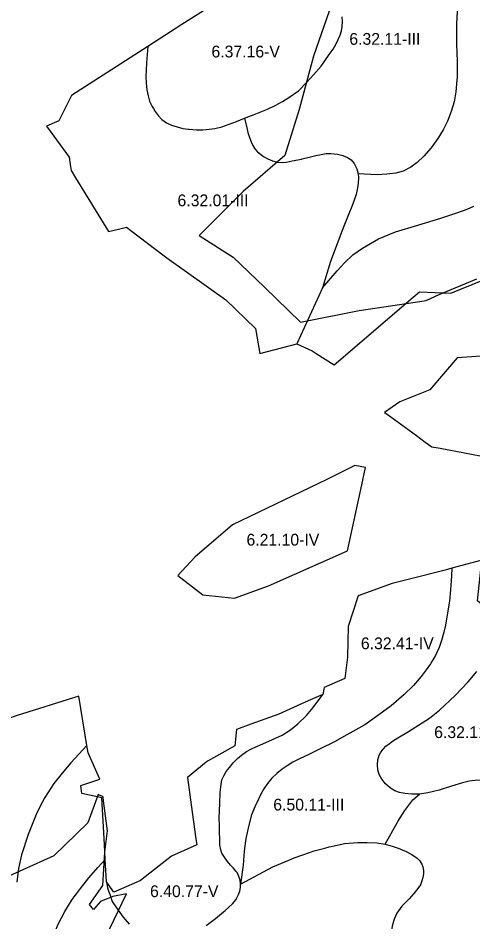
# Model space of a CAD drawing. Extents: x -555156 to -540209, y -1046851 to -1035695.
# Drawn here: x -543499 to -543114, y -1038962 to -1038196 of the extents above; entities that cross this region are included whole.
import ezdxf

# ---------------------------------------------------------------- set-up
doc = ezdxf.new("R2010")
doc.units = 0
for name, color, linetype in [('Vrstva 27', 7, 'Continuous'), ('Vrstva 28', 7, 'Continuous'), ('Vrstva 29', 7, 'Continuous')]:
    doc.layers.add(name, color=color, linetype=linetype)

msp = doc.modelspace()

# ---------------------------------------------------------------- linework, layer by layer
at = {"layer": 'Vrstva 28'}
for points in [[(-543306.54, -1038145.7), (-543311.34, -1038156.06), (-543320.71, -1038176.28), (-543360.37, -1038201.68), (-543389.3, -1038220.26)], [(-543126.82, -1038185.64), (-543127.72, -1038201.18), (-543127.57, -1038220.01), (-543127.42, -1038224.12), (-543127.31, -1038227.25), (-543127.16, -1038231.32), (-543127.16, -1038244.58), (-543127.16, -1038246.41), (-543127.36, -1038248.77), (-543128.2, -1038258.67), (-543129.55, -1038267.33), (-543132.09, -1038275.4), (-543135.37, -1038283.62), (-543138.96, -1038290.95), (-543143.59, -1038298.42), (-543149.26, -1038306.34)], [(-543307.24, -1038281.11), (-543297.76, -1038277.43), (-543287.86, -1038273.42), (-543281.37, -1038270.34), (-543275.14, -1038267.01), (-543269.68, -1038263.59), (-543261.65, -1038257.96), (-543254.66, -1038250.96), (-543248.77, -1038244.47), (-543242.45, -1038237.12), (-543235.45, -1038227.13), (-543232.28, -1038222.61), (-543229.89, -1038218.51), (-543227.84, -1038214.5), (-543226.22, -1038210.82), (-543225.03, -1038207.07), (-543224.51, -1038203.39), (-543224.34, -1038199.29), (-543224.69, -1038195.19)], [(-543389.3, -1038220.26), (-543453.96, -1038261.78), (-543464.75, -1038283.22), (-543475.03, -1038287.86), (-543468.76, -1038296.39), (-543455.75, -1038314.11), (-543454.92, -1038320.27), (-543454.23, -1038325.37), (-543450.41, -1038331.59), (-543422.48, -1038377.07), (-543414.21, -1038375.05), (-543407.26, -1038373.36), (-543403.54, -1038376.2), (-543375.29, -1038397.75), (-543373.03, -1038399.46), (-543323.25, -1038434.93), (-543297.87, -1038459.37), (-543294.19, -1038480.59), (-543263.03, -1038472.23)], [(-543389.3, -1038220.26), (-543390.36, -1038234.02), (-543390.61, -1038240.57), (-543390.78, -1038245.69), (-543390.53, -1038251.5), (-543389.93, -1038257.05), (-543388.99, -1038262.09), (-543387.71, -1038266.79), (-543385.58, -1038271.23), (-543384.5, -1038272.96), (-543383.04, -1038275.31), (-543380.39, -1038278.72), (-543377.23, -1038282.14), (-543373.48, -1038284.96), (-543369.12, -1038287.09), (-543364.43, -1038288.54), (-543359.65, -1038289.74), (-543355.11, -1038290.37), (-543354.1, -1038290.51)], [(-543342.75, -1038290.85), (-543336.86, -1038290.51), (-543332.59, -1038289.91), (-543326.53, -1038288.37), (-543320.3, -1038286.24), (-543314.16, -1038283.85), (-543307.24, -1038281.11)], [(-543307.24, -1038281.11), (-543305.22, -1038289.31), (-543304.36, -1038293.15), (-543303.17, -1038297.34), (-543301.8, -1038301.1), (-543300.35, -1038304.26), (-543298.64, -1038306.96), (-543298.56, -1038307.08), (-543296.62, -1038309.22), (-543296.17, -1038309.72), (-543291.3, -1038313.48), (-543287.55, -1038315.61), (-543283.71, -1038317.32), (-543279.44, -1038318.26), (-543275.34, -1038318.52), (-543272.01, -1038318.26), (-543266.89, -1038317.32), (-543258.98, -1038315.7), (-543258.53, -1038315.61), (-543252.55, -1038314.16), (-543251.26, -1038313.82), (-543246.75, -1038312.63), (-543242.42, -1038311.79), (-543238.06, -1038311.11), (-543234.05, -1038311.11), (-543228.51, -1038311.62), (-543223.98, -1038312.65), (-543220.14, -1038314.44), (-543216.98, -1038316.49), (-543214.51, -1038319.48), (-543212.2, -1038324.09), (-543211.01, -1038328.19)], [(-543354.1, -1038290.51), (-543348.04, -1038290.93), (-543342.75, -1038290.85)], [(-543149.26, -1038306.34), (-543155.39, -1038313.22), (-543160.91, -1038318.6), (-543166.44, -1038322.63), (-543173.01, -1038325.92), (-543178.99, -1038327.56), (-543186.6, -1038328.61), (-543194.82, -1038329.06), (-543211.01, -1038328.19)], [(-543211.01, -1038328.19), (-543210.75, -1038331.69), (-543210.92, -1038336.13), (-543211.61, -1038339.98), (-543212.8, -1038345.78), (-543215.79, -1038354.41), (-543223.17, -1038372.69), (-543234.41, -1038402.5), (-543241.2, -1038424.73)], [(-543241.2, -1038424.73), (-543228.73, -1038410.4), (-543222.45, -1038403.53), (-543215.43, -1038396.8), (-543207.37, -1038391.12), (-543193.77, -1038383.35), (-543179.44, -1038377.37), (-543160.47, -1038371.69), (-543141.05, -1038365.72), (-543126.56, -1038360.93), (-543118.57, -1038358.1), (-543113.04, -1038355.55)], [(-543263.03, -1038472.23), (-543250.1, -1038478.12), (-543246.54, -1038480.4), (-543231.45, -1038490.04), (-543164.36, -1038432.83), (-543158.92, -1038428.19), (-543132.38, -1038429.44), (-543105.34, -1038418.33), (-543080.91, -1038423.27), (-543024.69, -1038431.13), (-543021.95, -1038430.62), (-543016.98, -1038429.69), (-543005.4, -1038427.54)], [(-543241.2, -1038424.73), (-543263.03, -1038472.23)], [(-542912.45, -1038432.16), (-542946.17, -1038466.68), (-542990.21, -1038499.06), (-543028.67, -1038507.04), (-543056.48, -1038513.32), (-543057.35, -1038510.27), (-543067.77, -1038492.27), (-543090.66, -1038481.63), (-543127.25, -1038484.21), (-543150.42, -1038511.38), (-543175.81, -1038521.33), (-543188.66, -1038530.47), (-543186.57, -1038531.98), (-543161.63, -1038550.02), (-543154.1, -1038555.47), (-543148.54, -1038559.49), (-543141.66, -1038560.78), (-543100.26, -1038568.53)], [(-543287.03, -1038677.48), (-543220.04, -1038647.62), (-543207.87, -1038591.72), (-543204.7, -1038577.15), (-543213.92, -1038575.35), (-543237.55, -1038587.32), (-543317.53, -1038625.76), (-543349.47, -1038653.02), (-543363.91, -1038668.71), (-543342.61, -1038685.04)], [(-543087.57, -1038708.69), (-543091.56, -1038705.35), (-543109.93, -1038689.94), (-543106.21, -1038655.66), (-543131.59, -1038662.42)], [(-543131.59, -1038662.42), (-543131.86, -1038668.88), (-543132.75, -1038680.83), (-543133.65, -1038690.25), (-543135.29, -1038700.26), (-543137.14, -1038710.77), (-543138.5, -1038716.49), (-543140.3, -1038723.58), (-543142.43, -1038729.64), (-543144.31, -1038733.91), (-543145.86, -1038736.87), (-543146.78, -1038738.61), (-543148.54, -1038741.38), (-543149.77, -1038743.3), (-543153.27, -1038748.6), (-543157.71, -1038754.15), (-543164.11, -1038761.83), (-543172.32, -1038769.75), (-543183.08, -1038779.02), (-543193.38, -1038786.64), (-543205.48, -1038795.16), (-543220.57, -1038803.53), (-543231.12, -1038809.52), (-543243.07, -1038815.34), (-543253.37, -1038820.43), (-543260.03, -1038823.77), (-543266.34, -1038826.84), (-543271.12, -1038829.75), (-543275.3, -1038832.56), (-543279.83, -1038836.32), (-543284.18, -1038840.42), (-543287.85, -1038844.78), (-543290.84, -1038849.22), (-543293.57, -1038854), (-543297.14, -1038861.71), (-543297.3, -1038862.08), (-543301.32, -1038871.27), (-543303.56, -1038880.24), (-543306.25, -1038891.45), (-543307.59, -1038902.21), (-543308.31, -1038914.01)], [(-543131.59, -1038662.42), (-543137.34, -1038663.95), (-543165.27, -1038671.06), (-543182.1, -1038675.34), (-543211.11, -1038685.71), (-543219.39, -1038711.71), (-543219.96, -1038737.86), (-543222.27, -1038755.98), (-543239.81, -1038763.44), (-543241.05, -1038769.29)], [(-543342.61, -1038685.04), (-543315.92, -1038687.81), (-543287.03, -1038677.48)], [(-543171.39, -1038853.4), (-543176.09, -1038852.46), (-543180.01, -1038850.92), (-543183.75, -1038848.75), (-543187.93, -1038845.25), (-543190.92, -1038841.15), (-543193.31, -1038837.13), (-543194.33, -1038833.12), (-543194.76, -1038829.02), (-543194.25, -1038824.75), (-543193.58, -1038821.92), (-543193.48, -1038821.51), (-543192.11, -1038818.77), (-543190.06, -1038815.95), (-543189.61, -1038815.48), (-543187.5, -1038813.31), (-543184.6, -1038810.92), (-543181.87, -1038809.04), (-543177.32, -1038806.11), (-543168.36, -1038800.65), (-543156.67, -1038793.56), (-543150.44, -1038789.37), (-543142.19, -1038782.69), (-543128.9, -1038770.29), (-543117.84, -1038758.63), (-543110.37, -1038749.96)], [(-543440.9, -1038812.65), (-543447.7, -1038770.92), (-543499.85, -1038787.23), (-543508.08, -1038790.04), (-543529.87, -1038797.48), (-543592.87, -1038819), (-543585.18, -1038878.96), (-543585.35, -1038882.89), (-543586.72, -1038882.37), (-543597.27, -1038878.34), (-543646.7, -1038859.49)], [(-543241.05, -1038769.29), (-543253.33, -1038774.78), (-543278.32, -1038785.94), (-543302.02, -1038794.69), (-543314.21, -1038799.19), (-543315.58, -1038812.87), (-543319.58, -1038815.13), (-543338.15, -1038825.61), (-543339.67, -1038826.85), (-543355.5, -1038839.81), (-543352.38, -1038862.99), (-543348.5, -1038891.8), (-543347.83, -1038896.74), (-543369.13, -1038906.45), (-543387.45, -1038920.91), (-543395.31, -1038927.11), (-543401.21, -1038929.62), (-543418.06, -1038936.78), (-543424.24, -1038928.03)], [(-543310.61, -1038930.05), (-543311.1, -1038926.78), (-543311.73, -1038924.34), (-543312.66, -1038921.95), (-543313.93, -1038919.99), (-543314.63, -1038919.04), (-543315.29, -1038918.14), (-543316.95, -1038916.33), (-543319.21, -1038913.98), (-543321.6, -1038910.99), (-543324.33, -1038907.32), (-543326.38, -1038903.99), (-543327.4, -1038900.91), (-543328.17, -1038897.15), (-543328.34, -1038892.68), (-543328.45, -1038885.36), (-543328.49, -1038882.96), (-543328.58, -1038880.33), (-543328.79, -1038873.85), (-543328.34, -1038861.89), (-543327.92, -1038852.26), (-543327.16, -1038845.59), (-543326.39, -1038841.84), (-543324.68, -1038837.74), (-543322.89, -1038834.75), (-543320.07, -1038831.16), (-543316.83, -1038827.32), (-543314.54, -1038825.03), (-543313.16, -1038823.65), (-543309.74, -1038820.74), (-543305.56, -1038817.84), (-543302.06, -1038815.79), (-543298.39, -1038814.08), (-543291.73, -1038811.14), (-543283.7, -1038807.59), (-543275.34, -1038804), (-543268.47, -1038799.37), (-543262.05, -1038794.14), (-543254.73, -1038787.26), (-543249.2, -1038780.54), (-543241.05, -1038769.29)], [(-543440.9, -1038812.65), (-543454.53, -1038827.33), (-543461.85, -1038836), (-543468.72, -1038844.97), (-543476.55, -1038856.77), (-543480.33, -1038864.11), (-543483.87, -1038870.97)], [(-543425.31, -1038909.28), (-543426.05, -1038896.39), (-543428.32, -1038856.88), (-543445.21, -1038853.37), (-543446.06, -1038846.44), (-543429.99, -1038841.27), (-543439.89, -1038818.85), (-543440.9, -1038812.65)], [(-543056.55, -1038860.56), (-543079.66, -1038848.97), (-543088.71, -1038845.38), (-543095.8, -1038843.33), (-543100.4, -1038842.65), (-543106.55, -1038842.14), (-543111.84, -1038842.39), (-543116.96, -1038842.99), (-543122.51, -1038844.18), (-543131.79, -1038847), (-543142.4, -1038850.44), (-543151.96, -1038852.83), (-543159.1, -1038853.91)], [(-543188.03, -1038896.26), (-543177.56, -1038877.56), (-543177.27, -1038877.05), (-543171.45, -1038867.63), (-543164.73, -1038858.66), (-543159.1, -1038853.91)], [(-543159.1, -1038853.91), (-543165.5, -1038853.91), (-543171.39, -1038853.4)], [(-543483.87, -1038870.97), (-543490.59, -1038888.01), (-543496.12, -1038905.35), (-543498.66, -1038916.85), (-543500.33, -1038928.3)], [(-543310.61, -1038930.05), (-543283.2, -1038915.37), (-543269.88, -1038909.87), (-543265.12, -1038907.9), (-543257.97, -1038905.37), (-543248.24, -1038901.92), (-543239.37, -1038899.61), (-543235.53, -1038898.61), (-543233.9, -1038898.19), (-543222.55, -1038895.64), (-543211.35, -1038894.75), (-543203.3, -1038894.73), (-543195.28, -1038895.15), (-543188.03, -1038896.26)], [(-543188.03, -1038896.26), (-543182.31, -1038897.89), (-543177.02, -1038899.68), (-543170.36, -1038902.41), (-543165.41, -1038905.06), (-543161.1, -1038908.01), (-543158.62, -1038910.45), (-543156.96, -1038913.14), (-543156.08, -1038915.48), (-543155.54, -1038918.41), (-543155.59, -1038921.48), (-543156.13, -1038924.6), (-543157.06, -1038927.39), (-543158.32, -1038930.56), (-543160.32, -1038933.83), (-543163.74, -1038938.02), (-543167.93, -1038942.46), (-543173.9, -1038948.69), (-543178.25, -1038954.75), (-543180.47, -1038959.88), (-543182.27, -1038965.68), (-543183.46, -1038972.77)], [(-543470.41, -1038976.57), (-543465.2, -1038963.96), (-543459.67, -1038953.2), (-543453.4, -1038943.18), (-543451.55, -1038940.75), (-543449.67, -1038938.28), (-543447.17, -1038935.01), (-543446.23, -1038933.77), (-543439.21, -1038924.8), (-543431.59, -1038915.98), (-543425.31, -1038909.28)], [(-543424.24, -1038928.03), (-543425.31, -1038909.28)], [(-543308.31, -1038914.01), (-543310.61, -1038930.05)], [(-543424.24, -1038928.03), (-543423.5, -1038933.15), (-543421.95, -1038937.35), (-543421.45, -1038938.7), (-543419.31, -1038944.68), (-543415.82, -1038950.23), (-543410.18, -1038958.09), (-543404.98, -1038963.9)], [(-543311.13, -1038936.01), (-543310.9, -1038934.52), (-543310.61, -1038932.63), (-543310.61, -1038930.05)], [(-543339.73, -1038965.05), (-543331.96, -1038959.16), (-543325.15, -1038953.59), (-543323.6, -1038952.33), (-543317.37, -1038946.69), (-543314.38, -1038943.02), (-543313.97, -1038942.23), (-543312.33, -1038939), (-543311.13, -1038936.01)]]:
    msp.add_lwpolyline(points, dxfattribs=at)
at = {"layer": 'Vrstva 29'}
for points in [[(-543231.143982, -1038177.249023), (-543248.856995, -1038228.564026), (-543261.127014, -1038273.776978), (-543273.042908, -1038312.651001), (-543308.427979, -1038343.137024), (-543345.758911, -1038380.572998), (-543316.859985, -1038398.919006), (-543290.412903, -1038424.166016), (-543259.797913, -1038453.895996), (-543210.055969, -1038444.174011), (-543155.070984, -1038435.723999), (-543152.801758, -1038435.306221), (-543142.51, -1038430.51), (-543110.57, -1038417.09)], [(-543407.38815, -1038938.413605), (-543418.92, -1038940.49), (-543429.27, -1038944.78), (-543435.32, -1038951.47), (-543438.78, -1038947.22), (-543427.44, -1038931.29), (-543425.55, -1038903.13), (-543423.35, -1038885), (-543426.75, -1038859.61), (-543426.99, -1038856.04), (-543431.207157, -1038854.047403), (-543440.113993, -1038878.019994), (-543468.878005, -1038906.086995), (-543512.683008, -1038925.816002)], [(-543503.511997, -1039149.268002), (-543480.035005, -1039096.470007), (-543459.917007, -1039052.015992), (-543435.788001, -1038997.751995), (-543407.38815, -1038938.413605)]]:
    msp.add_lwpolyline(points, dxfattribs=at)

# ---------------------------------------------------------------- texts
at = {"layer": 'Vrstva 27'}
for s, p in [('6.32.11-III', (-543218.496548, -1038218.91)), ('6.37.16-V', (-543335.307974, -1038229.62)), ('6.32.01-III', (-543364.066548, -1038355.71)), ('6.21.10-IV', (-543305.62707, -1038643.27)), ('6.32.41-IV', (-543208.687241, -1038731.07)), ('6.32.11-III', (-543146.596548, -1038806.32)), ('6.50.11-III', (-543282.936548, -1038867.71)), ('6.40.77-V', (-543387.342993, -1038941.11))]:
    msp.add_text(s, height=10, dxfattribs=at).set_placement(p)

doc.saveas('drawing.dxf')
